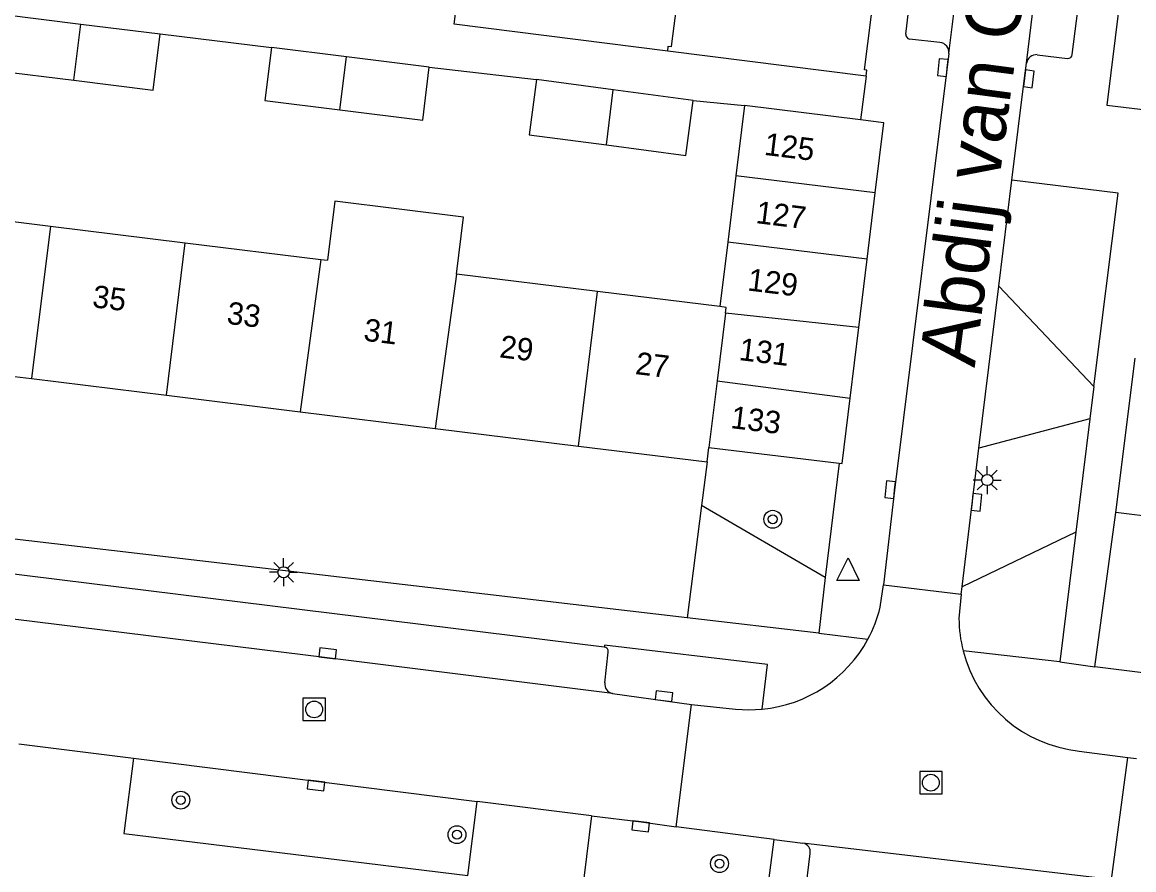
# Model space of a CAD drawing. Extents: x 131000 to 133014, y 396499 to 399001.
# Drawn here: x 131822.04 to 131871.69, y 397186.5 to 397224.37 of the extents above; entities that cross this region are included whole.
import ezdxf

# ---------------------------------------------------------------- set-up
doc = ezdxf.new("R2010")
doc.units = 0
for name, color, linetype in [('gg-afsc-erfafscheiding', 7, 'Continuous'), ('gg-anno-huisnummerreeks BGT', 7, 'Continuous'), ('gg-anno-openbare ruimte label', 7, 'Continuous'), ('gg-bbg-bijgebouw', 7, 'Continuous'), ('gg-bbg-gedigitaliseerde bebouwing', 7, 'Continuous'), ('gg-bbg-gedigitaliseerde bijgebouw', 7, 'Continuous'), ('gg-bbg-hoofdgebouw', 7, 'Continuous'), ('gg-bbg-tussenscheiding', 7, 'Continuous'), ('gg-knt-verharding', 7, 'Continuous'), ('gg-knt-verharding nz', 7, 'Continuous'), ('gt-grn-groengrens', 7, 'Continuous'), ('gt-grn-weggrens', 7, 'Continuous'), ('gt-symb-boom', 7, 'Continuous'), ('gt-symb-kolk', 7, 'Continuous'), ('gt-symb-lichtmast', 7, 'Continuous'), ('gt-symb-rioolschacht', 7, 'Continuous'), ('gt-symb-waterafsluiter', 7, 'Continuous')]:
    doc.layers.add(name, color=color, linetype=linetype)

# ---------------------------------------------------------------- blocks, each defined once
blk = doc.blocks.new('gt0-LMAST')
at = {"layer": 'gt-symb-lichtmast'}
for p, q in [((-0.005, 0.246), (-0.005, 0.621)), ((-0.182, 0.173), (-0.447, 0.438)), ((0.172, 0.173), (0.437, 0.438)), ((-0.255, -0.004), (-0.63, -0.004)), ((-0.182, -0.181), (-0.447, -0.446)), ((-0.005, -0.254), (-0.005, -0.629)), ((0.437, -0.446), (0.172, -0.181)), ((0.245, -0.004), (0.62, -0.004))]:
    blk.add_line(p, q, dxfattribs=at)
blk.add_circle((-0.005, -0.004), 0.25, dxfattribs=at)
blk = doc.blocks.new('gt0-KOLK')
at = {"layer": 'gt-symb-kolk'}
blk.add_lwpolyline([(0, 0), (0.375, 0), (0.375, 0.4), (-0.375, 0.4), (-0.375, 0), (0, 0)], dxfattribs=at)
blk = doc.blocks.new('gt0-BOOM')
at = {"layer": 'gt-symb-boom'}
for radius in [0.4, 0.2]:
    blk.add_circle((0, 0), radius, dxfattribs=at)
blk = doc.blocks.new('gt0-WAFSL')
at = {"layer": 'gt-symb-waterafsluiter'}
for p, q in [((-0.5, -0.333), (0, 0.667)), ((0, 0.667), (0.5, -0.333)), ((0.5, -0.333), (-0.5, -0.333))]:
    blk.add_line(p, q, dxfattribs=at)
blk = doc.blocks.new('gt0-RS')
at = {"layer": 'gt-symb-rioolschacht'}
blk.add_lwpolyline([(-0.5, -0.5), (0.5, -0.5), (0.5, 0.5), (-0.5, 0.5)], close=True, dxfattribs=at)
blk.add_circle((0, 0), 0.375, dxfattribs=at)

msp = doc.modelspace()

# ---------------------------------------------------------------- linework, layer by layer
at = {"layer": 'gg-afsc-erfafscheiding'}
for p, q in [((131828.202, 397223.854), (131833.178, 397223.248)), ((131840.226, 397222.373), (131845.009, 397221.81)), ((131852.007, 397220.882), (131854.305, 397220.647))]:
    msp.add_line(p, q, dxfattribs=at)
msp.add_lwpolyline([(131850.875, 397223.086), (131841.331, 397224.282), (131841.791, 397227.953)], dxfattribs=at)
at = {"layer": 'gg-bbg-bijgebouw'}
for p, q in [((131821.111, 397224.728), (131824.661, 397224.291)), ((131824.661, 397224.291), (131828.202, 397223.854)), ((131860.146, 397216.753), (131860.53, 397219.88)), ((131859.782, 397213.784), (131860.146, 397216.753)), ((131859.406, 397210.729), (131859.782, 397213.784)), ((131859.018, 397207.568), (131859.406, 397210.729)), ((131858.66, 397204.65), (131859.018, 397207.568)), ((131852.71, 397205.37), (131858.537, 397204.665)), ((131858.537, 397204.665), (131858.66, 397204.65))]:
    msp.add_line(p, q, dxfattribs=at)
at = {"layer": 'gg-bbg-gedigitaliseerde bebouwing'}
for p, q in [((131851.051, 397223.286), (131851.783, 397229.17)), ((131847.743, 397212.34), (131841.436, 397213.117)), ((131853.199, 397211.668), (131847.743, 397212.34))]:
    msp.add_line(p, q, dxfattribs=at)
msp.add_lwpolyline([(131841.436, 397213.117), (131841.75, 397215.668), (131836.004, 397216.376), (131835.679, 397213.739)], dxfattribs=at)
at = {"layer": 'gg-bbg-gedigitaliseerde bijgebouw'}
for p, q in [((131836.528, 397222.832), (131833.178, 397223.248)), ((131840.226, 397222.373), (131836.528, 397222.832)), ((131820.795, 397222.219), (131824.352, 397221.781)), ((131848.439, 397221.355), (131845.009, 397221.81)), ((131852.007, 397220.882), (131848.439, 397221.355)), ((131854.305, 397220.647), (131853.919, 397217.517)), ((131859.493, 397220.008), (131854.305, 397220.647)), ((131860.53, 397219.88), (131859.493, 397220.008)), ((131853.919, 397217.517), (131853.554, 397214.547)), ((131853.554, 397214.547), (131853.199, 397211.668))]:
    msp.add_line(p, q, dxfattribs=at)
for points in [[(131824.352, 397221.781), (131827.893, 397221.345), (131828.202, 397223.854)], [(131833.178, 397223.248), (131832.883, 397220.871), (131836.225, 397220.456)], [(131836.225, 397220.456), (131839.931, 397219.996), (131840.226, 397222.373)], [(131845.009, 397221.81), (131844.682, 397219.349), (131848.133, 397218.891)], [(131848.133, 397218.891), (131851.68, 397218.421), (131852.007, 397220.882)]]:
    msp.add_lwpolyline(points, dxfattribs=at)
at = {"layer": 'gg-bbg-hoofdgebouw'}
for p, q in [((131859.735, 397221.97), (131850.875, 397223.086)), ((131823.299, 397215.266), (131829.325, 397214.523)), ((131829.325, 397214.523), (131835.383, 397213.775)), ((131835.383, 397213.775), (131835.679, 397213.739)), ((131816.58, 397209.17), (131822.45, 397208.447)), ((131870.89, 397202.46), (131871.761, 397209.368)), ((131822.45, 397208.447), (131828.484, 397207.704)), ((131828.484, 397207.704), (131834.46, 397206.968)), ((131834.46, 397206.968), (131840.494, 397206.225)), ((131840.494, 397206.225), (131846.89, 397205.437)), ((131846.89, 397205.437), (131852.63, 397204.73)), ((131852.63, 397204.73), (131852.71, 397205.37)), ((131876.903, 397201.711), (131870.89, 397202.46))]:
    msp.add_line(p, q, dxfattribs=at)
for points in [[(131859.735, 397221.97), (131859.769, 397222.238), (131859.66, 397222.252), (131860.107, 397225.798), (131860.216, 397225.784), (131860.25, 397226.052), (131859.406, 397226.158), (131859.656, 397228.183)], [(131850.875, 397223.086), (131850.902, 397223.304), (131851.051, 397223.286)], [(131817.644, 397216.073), (131817.722, 397216.063), (131817.709, 397215.956), (131823.299, 397215.266)]]:
    msp.add_lwpolyline(points, dxfattribs=at)
at = {"layer": 'gg-bbg-tussenscheiding'}
for p, q in [((131824.352, 397221.781), (131824.661, 397224.291)), ((131836.225, 397220.456), (131836.528, 397222.832)), ((131848.133, 397218.891), (131848.439, 397221.355)), ((131860.146, 397216.753), (131853.919, 397217.517)), ((131823.299, 397215.266), (131822.45, 397208.447)), ((131828.484, 397207.704), (131829.325, 397214.523)), ((131859.782, 397213.784), (131853.554, 397214.547)), ((131835.383, 397213.775), (131834.46, 397206.968)), ((131841.436, 397213.117), (131840.494, 397206.225)), ((131846.89, 397205.437), (131847.743, 397212.34)), ((131853.461, 397211.379), (131853.082, 397208.344)), ((131859.406, 397210.729), (131853.461, 397211.379)), ((131853.082, 397208.344), (131852.71, 397205.37)), ((131853.082, 397208.344), (131859.018, 397207.568))]:
    msp.add_line(p, q, dxfattribs=at)
msp.add_lwpolyline([(131853.461, 397211.379), (131853.492, 397211.624), (131853.199, 397211.668)], dxfattribs=at)
at = {"layer": 'gg-knt-verharding'}
for p, q in [((131861.505, 397223.842), (131864.186, 397245.722)), ((131868.947, 397222.931), (131871.653, 397244.802)), ((131863.03, 397223.473), (131861.679, 397223.622)), ((131867.384, 397222.924), (131868.739, 397222.755)), ((131865.659, 397212.58), (131866.244, 397217.315)), ((131864.766, 397205.345), (131865.659, 397212.58)), ((131869.913, 397208.1), (131869.735, 397206.653)), ((131869.735, 397206.653), (131869.107, 397201.593)), ((131864.026, 397199.139), (131864.766, 397205.345)), ((131852.63, 397204.73), (131852.384, 397202.778)), ((131858.537, 397204.665), (131857.91, 397199.565)), ((131852.384, 397202.778), (131851.75, 397197.76)), ((131869.95, 397195.57), (131870.89, 397202.46)), ((131851.75, 397197.76), (131815.58, 397201.99)), ((131869.107, 397201.593), (131868.388, 397195.793)), ((131848.037, 397196.445), (131816.213, 397200.389)), ((131857.91, 397199.565), (131857.619, 397197.074)), ((131860.371, 397198.234), (131860.513, 397199.229)), ((131860.513, 397199.229), (131863.988, 397198.816)), ((131863.988, 397198.816), (131864.026, 397199.139)), ((131863.988, 397198.816), (131863.885, 397197.727)), ((131857.619, 397197.074), (131851.75, 397197.76)), ((131848.07, 397194.861), (131848.215, 397196.228)), ((131868.388, 397195.793), (131864.069, 397196.289)), ((131905.98, 397191.09), (131869.95, 397195.57)), ((131848.404, 397194.374), (131851.936, 397193.889)), ((131851.253, 397188.423), (131851.936, 397193.889)), ((131821.893, 397192.131), (131827.009, 397191.489)), ((131869.258, 397191.807), (131871.424, 397191.519)), ((131827.009, 397191.489), (131842.364, 397189.558)), ((131870.701, 397186.07), (131871.424, 397191.519)), ((131871.424, 397191.519), (131871.82, 397191.467)), ((131847.464, 397188.915), (131842.364, 397189.558)), ((131855.631, 397187.856), (131851.253, 397188.423)), ((131855.631, 397187.856), (131856.916, 397187.691)), ((131870.701, 397186.07), (131856.916, 397187.691)), ((131856.649, 397182.504), (131857.239, 397187.23))]:
    msp.add_line(p, q, dxfattribs=at)
for points in [[(131876.42, 397268.58), (131870.49, 397220.67), (131873.35, 397220.32), (131873.346, 397220.289)], [(131863.436, 397222.976), (131861.007, 397203.46), (131860.513, 397199.229)], [(131866.244, 397217.315), (131866.806, 397221.87), (131866.903, 397222.549)], [(131869.913, 397208.1), (131870.993, 397216.729), (131866.244, 397217.315)], [(131855.089, 397193.671), (131855.326, 397195.672), (131848.048, 397196.536), (131848.037, 397196.445)], [(131851.936, 397193.889), (131853.901, 397193.673), (131854.495, 397193.643), (131855.089, 397193.671)], [(131827.009, 397191.489), (131826.587, 397188.122), (131841.946, 397186.248), (131842.364, 397189.558)], [(131847.464, 397188.915), (131846.795, 397183.463), (131854.932, 397182.459), (131855.631, 397187.856)], [(131847.464, 397188.915), (131849.689, 397188.637), (131851.253, 397188.423)]]:
    msp.add_lwpolyline(points, dxfattribs=at)
for centre, radius, start, end in [((131861.718, 397223.832), 0.214, 177.3143, 259.3673), ((131862.982, 397223.019), 0.456, 354.5349, 83.956), ((131867.347, 397222.476), 0.45, 85.273, 170.6088), ((131868.746, 397222.957), 0.202, 267.9034, 352.5693), ((131854.484, 397199.694), 6.065, 331.5323, 346.0711), ((131869.823, 397197.756), 5.938, 180.2805, 194.3029), ((131854.504, 397199.688), 6.045, 275.5565, 331.4985), ((131848.041, 397196.266), 0.179, 347.5998, 91.1226), ((131869.869, 397197.76), 5.984, 194.2267, 264.1356), ((131848.494, 397194.794), 0.429, 171.008, 257.8791), ((131856.846, 397187.299), 0.399, 350.0891, 79.945)]:
    msp.add_arc(centre, radius, start, end, dxfattribs=at)
at = {"layer": 'gg-knt-verharding nz'}
for p, q in [((131863.436, 397222.976), (131866.115, 397245.022)), ((131866.903, 397222.549), (131869.586, 397244.599)), ((131859.735, 397221.97), (131859.493, 397220.008))]:
    msp.add_line(p, q, dxfattribs=at)
msp.add_lwpolyline([(131848.404, 397194.374), (131835.663, 397195.97), (131818.606, 397198.073), (131815.312, 397198.494)], dxfattribs=at)
at = {"layer": 'gt-grn-groengrens'}
for p, q in [((131869.913, 397208.1), (131865.659, 397212.58)), ((131869.735, 397206.653), (131864.766, 397205.345)), ((131857.91, 397199.565), (131852.384, 397202.778)), ((131869.107, 397201.593), (131864.026, 397199.139))]:
    msp.add_line(p, q, dxfattribs=at)
at = {"layer": 'gt-grn-weggrens'}
for p, q in [((131857.619, 397197.074), (131859.816, 397196.803)), ((131868.388, 397195.793), (131869.95, 397195.57))]:
    msp.add_line(p, q, dxfattribs=at)

# ---------------------------------------------------------------- block references
at = {"layer": 'gt-symb-boom'}
for p in [(131855.568, 397202.164), (131829.126, 397189.612), (131841.462, 397188.069), (131853.188, 397186.774)]:
    msp.add_blockref('gt0-BOOM', p, dxfattribs=at)
at = {"layer": 'gt-symb-kolk'}
for p, rotation in [((131863.36, 397222.328), 84.00113167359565), ((131866.806, 397221.87), -96.99789501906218), ((131861.007, 397203.46), 84.00113167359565), ((131864.47, 397202.946), -95.99886832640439), ((131835.663, 397195.97), -6.997895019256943), ((131850.68, 397194.06), -6.997895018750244), ((131835.189, 397190.464), 173.0021049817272), ((131849.689, 397188.637), 173.00210498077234)]:
    msp.add_blockref('gt0-KOLK', p, dxfattribs=dict(at, rotation=rotation))
at = {"layer": 'gt-symb-lichtmast'}
for p in [(131865.151, 397203.919), (131833.722, 397199.799)]:
    msp.add_blockref('gt0-LMAST', p, dxfattribs=at)
at = {"layer": 'gt-symb-rioolschacht'}
for p in [(131835.083, 397193.667), (131862.629, 397190.392)]:
    msp.add_blockref('gt0-RS', p, dxfattribs=at)
at = {"layer": 'gt-symb-waterafsluiter'}
msp.add_blockref('gt0-WAFSL', (131858.932, 397199.766), dxfattribs=at)

# ---------------------------------------------------------------- texts
at = {"layer": 'gg-anno-huisnummerreeks BGT'}
for s, p in [('125', (131855.15, 397218.45)), ('127', (131854.776, 397215.401)), ('129', (131854.406, 397212.391)), ('35', (131825.142, 397211.642)), ('33', (131831.147, 397210.903)), ('31', (131837.258, 397210.15)), ('29', (131843.331, 397209.402)), ('131', (131854.024, 397209.282)), ('27', (131849.395, 397208.655)), ('133', (131853.651, 397206.242))]:
    msp.add_text(s, height=1, rotation=353, dxfattribs=at).set_placement(p)
at = {"layer": 'gg-anno-openbare ruimte label'}
msp.add_text('Abdij van Oosterhoutstraat', height=2.5, rotation=82.5, dxfattribs=at).set_placement((131864.584, 397208.914))

doc.saveas('drawing.dxf')
